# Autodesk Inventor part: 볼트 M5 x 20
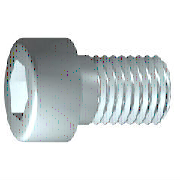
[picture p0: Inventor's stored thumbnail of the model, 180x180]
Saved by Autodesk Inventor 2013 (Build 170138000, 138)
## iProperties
Created: 2012-02
Part Number: 볼트 M5 x 20
Material: 스테인리스강
Description: 6각 소켓 머리 캡 나사
Document SubType Name: Modeling
Standard: ISO 4762
Designer: mduedu
Standard Revision: Fourth edition 2004-03-01
Standards Organization: ISO
Language: ko-KR
Size Designation: M5 x 20
Categories: <MemberInstance><Categories><Category DisplayName="조임쇠" InternalName="e4da775c-781d-43d5-af7c-5136215cf5a6" Mnemonic="FSTN"><Category DisplayName="볼트" InternalN
Density: 8.08 g/cm^3
Mass: 5.10181 g
Surface Area: 5.88237 cm^2
Volume: 0.631412 cm^3
IsCustomPart: 0
Author: mduedu
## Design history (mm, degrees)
sketch "스케치1"
  geometry: L1 (-1.167, 0)-(20, 0); L2 (20, 0)-(20, 2.5); L3 (20, 2.5)-(2, 2.5); L4 (2, 2.5)-(1.509, 2.5); L5 (1.509, 2.5)-(0, 2.5); L6 (0, 2.5)-(0, 4.25); L7 (0, 4.25)-(-5, 4.25); L8 (-5, 4.25)-(-5, 2.309); L9 (-5, 2.309)-(-2.5, 2.309); L10 (-2.5, 2.309)-(-1.167, 0); L11 (-10, 0)-(25, 0) reference; L12 (0, -0.85)-(0, 5.1) reference; L13 (2, 2.5)-(0, 2.5)
  constraints: 22 end point, 6 parallel, 2 collinear, 2 perpendicular, 1 horizontal, 1 point on line
  dimensions: "d1" = 18 distance from line of L3.end L2 (= GEL); "d2" = 0.49086 distance of L4.end L3.end (computed from GAL); "d3" = 5 distance between parallel lines of L8 L6 (= KOH); "d4" = 2.5 distance of L8.end L9.end (= INTI); "d5" = 60 deg angle of L10 L1; "d6" = 5 diameter of L3 L1 (= GD); "d7" = 5 diameter of L5 L1 (= BDM); "d8" = 4.6188 diameter of L9 L1 (= 1.1547 x SW); "d9" = 8.5 diameter of L7 L1 (= KOD); "d26" = 20 distance between parallel lines of L12 L2 (= NLG)
revolve "본체" sketch "스케치1" stored, may be unused: angle "d10" = 90 deg
sketch "스케치2"
  geometry: L1 (0, -5.95)-(0, 5.95) reference; L2 (-5.95, 0)-(5.95, 0) reference; L3 (2.309, 0)-(1.155, -2); L4 (1.155, -2)-(-1.155, -2); L5 (-1.155, -2)-(-2.309, 0); L6 (-2.309, 0)-(-1.155, 2); L7 (-1.155, 2)-(1.155, 2); L8 (1.155, 2)-(2.309, 0); 2 further points
  constraints: 12 end point, 1 coincident, 1 horizontal alignment, 1 point on line, 12 other
extrude "슬롯" join sketch "스케치2" stored distance "d11" = 10; taper "d12" = 0 deg
workplane "Work Plane1"
fillet "Fillet2" dims "d30" = 0.1 (= R)
body "Solid1"
fillet "모깎기1" dims "d17" = 0.5 (= RR)
feature "스레드" dims "d13" = 18 (= GEL), "d14" = 0
chamfer "모따기1" distance "d15" = 0.49076 (= -0.5 x SPD + 0.5 x GD); stored, may be unused: second distance "d16" = 0.49076 (= GUL), angle "d27" = 45 deg
other parameters: "GD" = 5 [user parameter; used in 2 equation terms], "NLG" = 20 [user parameter; used in 1 equation term], "GEL" = 18 [user parameter; used in 2 equation terms], "KOD" = 8.5 [user parameter; used in 1 equation term], "KOH" = 5 [user parameter; used in 1 equation term], "INTI" = 2.5 [user parameter; used in 1 equation term], "GAL" = 0.49076 (= 0.61345 x PTC) [user parameter; used in 1 equation term], "GUL" = 0.49076 (= 0.61345 x PTC) [user parameter; used in 1 equation term], "BDM" = 5 (= NND) [user parameter; used in 1 equation term], "SW" = 4 [user parameter; used in 2 equation terms], "RR" = 0.5 [user parameter; used in 1 equation term], "SPD" = 4.01848 (= NND - 1.2269 x PTC) [user parameter; used in 1 equation term], "d19" = 0, "d28" = 0, "d29" = 0, "R" = 0.1 [user parameter; used in 1 equation term], "TOA" = 30 deg [user parameter], "GD1" = 4.01848 (= THREADDIA - 1.2269 x PTC) [user parameter], "THREADDIA" = 5 [user parameter; used in 1 equation term], "FAWI" = 45 deg [user parameter], "TPU" = 12.5 (computed from PTC) [user parameter], "PTC" = 0.8 [user parameter; used in 5 equation terms], "NND" = 5 [user parameter; used in 2 equation terms], "E0" = 4.62 (= 1.155 x SW) [user parameter]
